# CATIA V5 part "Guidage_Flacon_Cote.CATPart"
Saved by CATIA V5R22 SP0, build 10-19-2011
Part number: Guidage_flacon_cote1
Bounding box of the stored display mesh (mm): x 0 to 5, y -49.5 to 49.5, z 0 to 15
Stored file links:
  C:\Users\La forge\Desktop\CAO_PER_pick&place_2023A\Sous_Ensemble_Flacon\Guidage_Flacon_Cote.CATPart
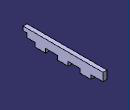
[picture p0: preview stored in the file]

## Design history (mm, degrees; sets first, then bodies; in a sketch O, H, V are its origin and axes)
Body1 (main body)
  Sketch1 on yz-plane, origin (0, 0, 0), H (0, 1, 0), V (0, 0, 1)
    point P1 (49.5, 0)
    line L1 (49.5, 0) -> (-49.5, 0)
    line L2 (-49.5, 0) -> (-49.5, 15)
    line L3 (-49.5, 15) -> (49.5, 15)
    line L4 (49.5, 15) -> (49.5, 0)
    length L3 = 99
    length L4 = 15
    coincidence: P1 H
    horizontal: L1 H, L3 H
    vertical: L2 V, L4 V
    equidistance: L4 L2 O
  Pad1: profile Sketch1, direction (1, 0, 0), length 5
  Sketch2 on end face of Pad1, origin (5, 0, 0), H (0, 1, 0), V (0, 0, 1)
    point P1 (-49.5, 0)
    line L1 (-49.5, 0) -> (-34.5, 0)
    line L2 (-34.5, 0) -> (-34.5, 5)
    line L3 (-34.5, 5) -> (-49.5, 5)
    line L4 (-49.5, 5) -> (-49.5, 0)
    reference projected point E1 (-49.5, 0) from vertex [face of Pad1 from Sketch1.L1 | end face of Pad1 | face of Pad1 from Sketch1.L2]
    length L2 = 5
    length L3 = 15
    coincidence: P1 H, P1 E1
    horizontal: L1 H, L3 H
    vertical: L2 V, L4 V
  Pocket1: profile Sketch2, direction (-1, 0, 0), through (limit type 3)
  RectPattern1: of Pocket1, direction 1 instances 4, spacing 28, along end face of Pad1
  Sketch3 on end face of Pad1, origin (5, 0, 0), H (0, 1, 0), V (0, 0, 1)
    line L1 (-44.5, 5) -> (-49.5, 5)
    line L2 (-49.5, 5) -> (-49.5, 10)
    line L3 (-49.5, 10) -> (-44.5, 10)
    line L4 (-44.5, 10) -> (-44.5, 5)
    reference projected line E1 (-34.5, 5) -> (-49.5, 5) from edge [end face of Pad1 | face of Pocket1 from Sketch2.L3]
    reference projected line E2 (-49.5, 15) -> (-49.5, 0) from edge [face of Pad1 from Sketch1.L2 | end face of Pad1]
    length L2 = 5
    length L3 = 5
    horizontal: L1 H, L3 H
    vertical: L2 V, L4 V
    coincidence: L1 E1, L2 E2
  Pocket2: profile Sketch3, direction (-1, 0, 0), through (limit type 3)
